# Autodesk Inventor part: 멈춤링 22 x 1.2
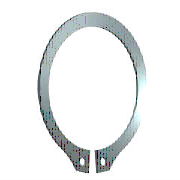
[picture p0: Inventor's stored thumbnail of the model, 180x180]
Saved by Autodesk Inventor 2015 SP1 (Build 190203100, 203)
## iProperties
IsCustomPart: 0
Company: 한국ATC센터
Created: 2014-07
Part Number: 멈춤링 22 x 1.2
Material: Steel, Mild
Description: 리테이닝 링(C형)
Document SubType Name: Modeling
Standard: KS B 1336
Designer: KYOUNG IL JANG
Standards Organization: KS
Language: ko-KR
Size Designation: 22 x 1.2
Categories: <MemberInstance><Categories><Category DisplayName="샤프트 부품" InternalName="7f7aeb1f-a693-4053-b835-cee3144e0d98" Mnemonic="SHFT"><Category DisplayName="써클립" Inter
Density: 7.86 g/cm^3
Appearance: Metal-Steel
Mass: 1.8286 g
Surface Area: 5.91219 cm^2
Volume: 0.232646 cm^3
Author: KYOUNG IL JANG
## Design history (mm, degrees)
sketch "스케치1"
  geometry: L1 (-6, 0)-(6, 0) reference; L2 (0, 20.189)-(0, -80.536) reference; L3 (-48.09, 0)-(48.09, 0) reference; L4 (-0.5, -21.488)-(-0.5, -25.588); L5 (-0.5, -6.54)-(-0.5, -13.29); L6 (-2.795, 2.7)-(3.672, 2.7); L7 (0.5, -6.54)-(0.5, -13.29); L8 (0.5, -21.488)-(0.5, -25.588); C1 r 1 at (-2, -23.437); C2 r 1 at (2, -23.437); A1 r 10.5 centre (0, -11) between (0.5, -21.488) and (-0.5, -21.488); A2 r 13.025 centre (0, -10.325) between (5.149, -22.289) and (-5.149, -22.289); A3 r 14.597 centre (0, -11) between (-2.318, -25.411) and (-0.5, -25.588); A4 r 2 centre (-2, -23.437) between (-3.97, -23.781) and (-2.318, -25.411); A5 r 2 centre (-5.94, -24.126) between (-3.97, -23.781) and (-5.149, -22.289); A6 r 2 centre (5.94, -24.126) between (5.149, -22.289) and (3.97, -23.781); A7 r 2 centre (2, -23.437) between (2.318, -25.411) and (3.97, -23.781); A8 r 14.597 centre (0, -11) between (0.5, -25.588) and (2.318, -25.411)
  constraints: 16 point on circle, 12 end point, 10 centre point, 9 symmetric about line, 5 point on line, 4 tangent, 3 coincident, 2 horizontal, 1 perpendicular, 1 vertical, 5 other
  dimensions: "d0" = 21 diameter of A1 (= ND); "d1" = 4.1 distance of L4.end L4.start (= SRB2); "d6" = 0.5 distance between parallel lines of L2 L5 (= 0.25 x SD5); "d7" = 2.7 distance between parallel lines of L6 L3 (= SRB1); "d8" = 0.675 distance of A1.centre A2.centre (= 0.25 x SRB1); "d9" = 2 radius of A4 (= SD5); "d10" = 2 radius of A5 (= SD5); "d11" = 1.5 distance from line of L4 A4.centre (= 0.75 x SD5); "d12" = 2 diameter of C1 (= SD5); "d13" = 2 diameter of C2 (= SD5); "d14" = 11 distance from line of A1.centre L1 (= 0.5 x WD)
extrude "본체" new body sketch "스케치1" distance "d2" = 1.2 (= SD); taper "d3" = 0 deg
workaxis "Work Axis1"
workplane "Work Plane1"
body "Solid1"
other parameters: "WD" = 22 (= WDMIN) [user parameter; used in 1 equation term], "SD" = 1.2 [user parameter; used in 1 equation term], "SRB1" = 2.7 [user parameter; used in 2 equation terms], "ND" = 21 [user parameter; used in 1 equation term], "SRB2" = 4.1 [user parameter; used in 1 equation term], "SD5" = 2 [user parameter; used in 6 equation terms], "d15" = 0, "d16" = 0, "d17" = 0, "d41" = 0, "d42" = 0, "WDMIN" = 22 [user parameter; used in 1 equation term], "SD3" = 20.5 [user parameter], "WDMAX" = 24 [user parameter]
